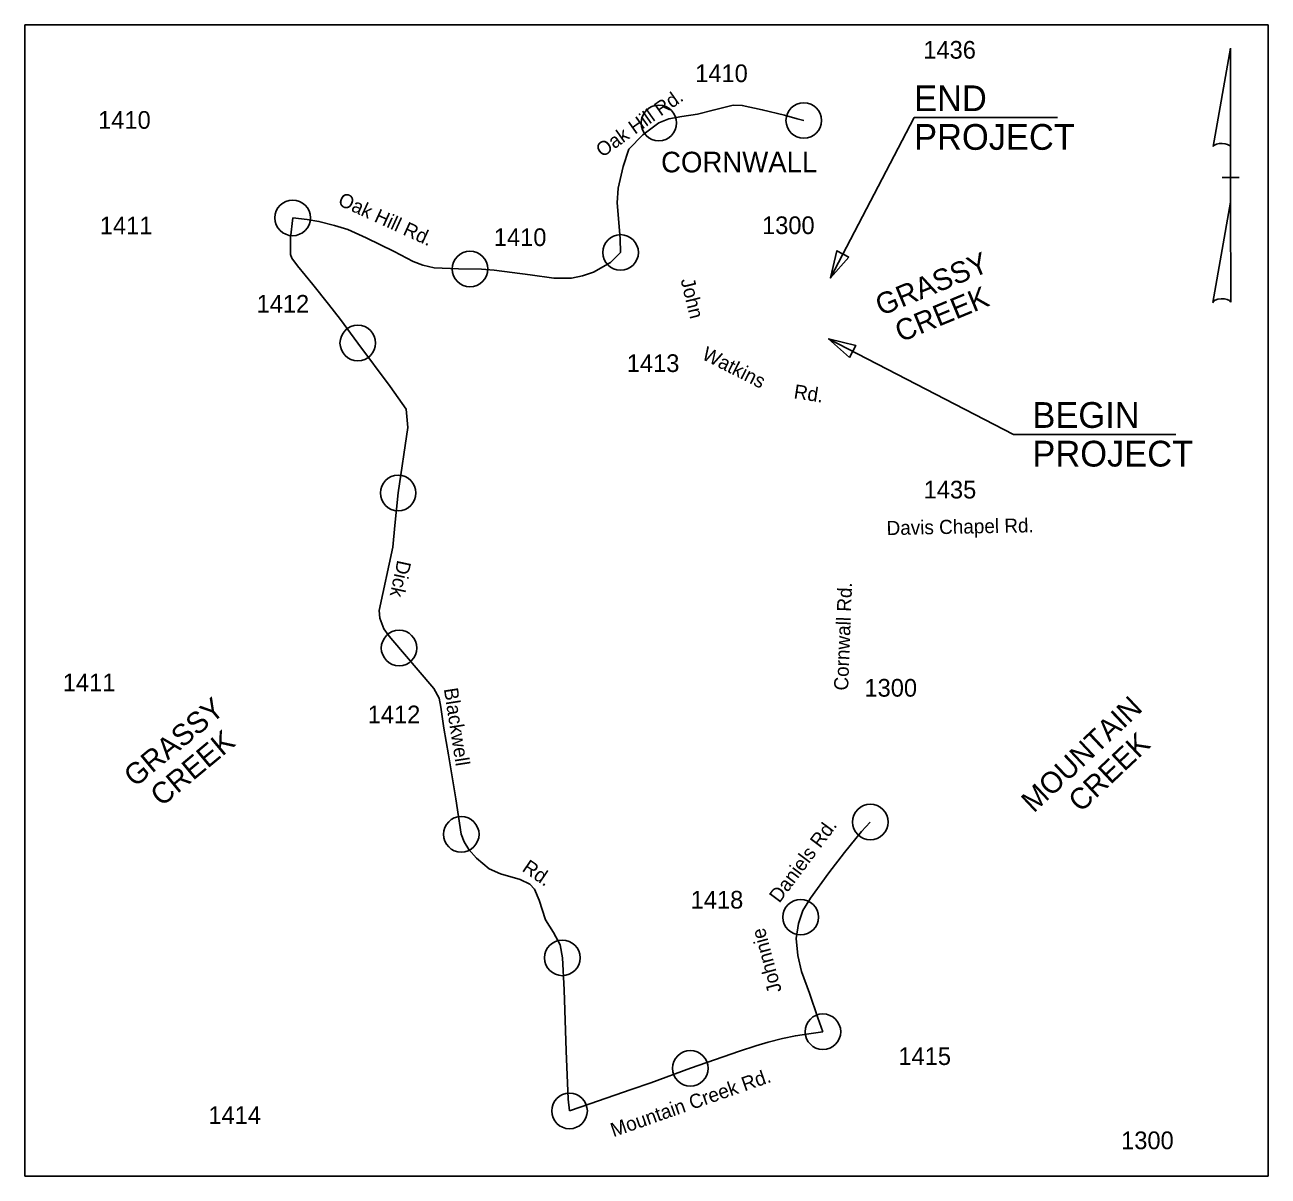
# Model space of a CAD drawing. Extents: x 2088807 to 2104187, y 980460 to 994694.
import ezdxf

# ---------------------------------------------------------------- set-up
doc = ezdxf.new("R2010")
doc.units = 0
for name, color, linetype in [('Exist Civil Demographics City Label', 7, 'Continuous'), ('Exist Hydrographic Creek Single Shore Label', 7, 'Continuous'), ('Exist Road Secondary Type 51 Label', 7, 'Continuous'), ('Exist Road Secondary Type 51 Number Label', 7, 'Continuous'), ('Old_Level_9', 7, 'Continuous'), ('Prop North Arrow for Plan Sheets CELL', 7, 'Continuous'), ('Sheet Block Title CELL', 7, 'Continuous'), ('Sheet Title CELL', 7, 'Continuous')]:
    doc.layers.add(name, color=color, linetype=linetype)

msp = doc.modelspace()

# ---------------------------------------------------------------- linework, layer by layer
at = {"layer": 'Old_Level_9'}
for p, q in [((2098772, 991565), (2099807, 993547)), ((2099807, 993547), (2101582, 993547)), ((2098750, 990810), (2101036, 989631)), ((2101036, 989631), (2103045, 989631))]:
    msp.add_line(p, q, dxfattribs=at)
for points in [[(2099001, 991822), (2098772, 991565), (2098853, 991900)], [(2099009, 990582), (2098750, 990810), (2099086, 990731)]]:
    msp.add_lwpolyline(points, close=True, dxfattribs=at)
at = {"layer": 'Prop North Arrow for Plan Sheets CELL'}
for p, q in [((2103507, 993190), (2103722, 994407)), ((2103723, 994407), (2103722, 994407)), ((2103723, 994407), (2103722, 994407)), ((2103723, 994407), (2103723, 993152)), ((2103723, 992501), (2103723, 993189)), ((2103723, 993152), (2103723, 993188)), ((2103618, 992806), (2103617, 992806)), ((2103712, 992806), (2103618, 992806)), ((2103620, 992806), (2103830, 992806)), ((2103723, 992501), (2103504, 991261)), ((2103725, 991266), (2103723, 992501))]:
    msp.add_line(p, q, dxfattribs=at)
for centre, start_param, end_param in [((2103615, 993177), 0.216388, 2.908219), ((2103615, 991257), 0.201328, 3.141593)]:
    msp.add_ellipse(centre, major_axis=(111, -1), ratio=0.461098, start_param=start_param, end_param=end_param, dxfattribs=at)
at = {"layer": 'Sheet Block Title CELL'}
msp.add_lwpolyline([(2088807, 994694), (2104187, 994694), (2104187, 980460), (2088807, 980460)], close=True, dxfattribs=at)
at = {"layer": 'Sheet Title CELL'}
for points in [[(2098442, 993511), (2098360, 993533), (2098204, 993576), (2097929, 993645), (2097682, 993697), (2097570, 993700), (2097320, 993641), (2097127, 993589), (2096932, 993559), (2096773, 993534), (2096649, 993481), (2096450, 993335), (2096277, 993156), (2096207, 992942), (2096148, 992676), (2096135, 992492), (2096153, 992250), (2096171, 992050), (2096176, 991880)], [(2092120, 992307), (2092094, 992059), (2092092, 991854), (2092109, 991808), (2092179, 991715), (2092370, 991483), (2092562, 991241), (2092710, 991053), (2092925, 990760), (2093326, 990221), (2093522, 989943), (2093544, 989715), (2093425, 988906), (2093385, 988506), (2093360, 988236), (2093190, 987455), (2093199, 987359), (2093247, 987227), (2093299, 987153), (2093333, 987110), (2093865, 986487), (2093933, 986369), (2093954, 986259), (2093989, 985997), (2094046, 985668), (2094140, 985124)], [(2096176, 991880), (2096052, 991754), (2095842, 991636), (2095705, 991591), (2095570, 991564), (2095352, 991564), (2095056, 991602), (2094614, 991660), (2094455, 991674), (2094171, 991677), (2093870, 991690), (2093730, 991724), (2093610, 991770), (2093376, 991893), (2093030, 992062), (2092802, 992164), (2092639, 992213), (2092444, 992263), (2092297, 992288), (2092120, 992307)], [(2094140, 985124), (2094205, 984686), (2094239, 984593), (2094298, 984500), (2094395, 984393), (2094552, 984259), (2094690, 984196), (2094935, 984128), (2095052, 984068), (2095111, 984008), (2095170, 983870), (2095248, 983627), (2095347, 983471), (2095427, 983319), (2095456, 983158), (2095479, 982762), (2095503, 982009), (2095528, 981413), (2095545, 981266)], [(2098679, 982245), (2098617, 982417), (2098512, 982721), (2098416, 982989), (2098369, 983188), (2098350, 983399), (2098378, 983583), (2098430, 983742), (2098525, 983897), (2098752, 984208), (2098944, 984460), (2099155, 984720), (2099265, 984838)], [(2095545, 981266), (2095797, 981353), (2096309, 981532), (2096549, 981614), (2097039, 981793), (2097648, 982006), (2097850, 982072), (2098001, 982116), (2098180, 982161), (2098339, 982195), (2098477, 982216), (2098679, 982245)]]:
    msp.add_lwpolyline(points, dxfattribs=at)
for centre in [(2098442, 993511), (2096649, 993481), (2092120, 992307), (2096176, 991880), (2094313, 991676), (2092925, 990760), (2093425, 988906), (2093436, 986989), (2099265, 984838), (2094205, 984686), (2098404, 983662), (2095456, 983158), (2098679, 982245), (2097039, 981793), (2095545, 981266)]:
    msp.add_circle(centre, 220, dxfattribs=at)

# ---------------------------------------------------------------- texts
at = {"layer": 'Exist Civil Demographics City Label'}
msp.add_text('CORNWALL', height=255, dxfattribs=at).set_placement((2096677, 992870))
at = {"layer": 'Exist Hydrographic Creek Single Shore Label'}
for s, rotation, p in [('GRASSY', 22.4756, (2099398, 991092)), ('CREEK', 22.4756, (2099640, 990766)), ('GRASSY', 39.8035, (2090170, 985259)), ('MOUNTAIN', 43.2868, (2101287, 984941)), ('CREEK', 39.8035, (2090498, 985020)), ('CREEK', 43.2868, (2101868, 984947))]:
    msp.add_text(s, height=262.5, rotation=rotation, dxfattribs=at).set_placement(p)
at = {"layer": 'Exist Road Secondary Type 51 Label'}
for s, rotation, p in [('Oak Hill Rd.', 35.197, (2095949, 993049)), ('Oak Hill Rd.', 335.4871, (2092667, 992472)), ('John', 283.9019, (2096917, 991540)), ('Watkins', 333.1694, (2097169, 990568)), ('Rd.', 351.2954, (2098311, 990078)), ('Davis Chapel Rd.', 1.1121, (2099468, 988385)), ('Dick', 257.7734, (2093416, 988084)), ('Cornwall Rd.', 87.846, (2098990, 986461)), ('Blackwell', 278.8375, (2093989, 986484)), ('Daniels Rd.', 53.2824, (2098140, 983827)), ('Rd.', 325.833, (2094946, 984239)), ('Johnnie', 105.1654, (2098171, 982750)), ('Mountain Creek Rd.', 19.2846, (2096088, 980940))]:
    msp.add_text(s, height=175, rotation=rotation, dxfattribs=at).set_placement(p)
at = {"layer": 'Exist Road Secondary Type 51 Number Label'}
for s, p in [('1436', (2099921, 994276)), ('1410', (2097099, 993986)), ('1410', (2089713, 993409)), ('1411', (2089734, 992104)), ('1300', (2097926, 992107)), ('1410', (2094608, 991959)), ('1412', (2091673, 991136)), ('1413', (2096253, 990402)), ('1435', (2099925, 988838)), ('1411', (2089276, 986455)), ('1300', (2099193, 986388)), ('1412', (2093048, 986059)), ('1418', (2097043, 983768)), ('1415', (2099613, 981834)), ('1414', (2091077, 981105)), ('1300', (2102368, 980793))]:
    msp.add_text(s, height=218.7, dxfattribs=at).set_placement(p)
at = {"layer": 'Old_Level_9'}
for s, p in [('END', (2099807, 993627)), ('PROJECT', (2099807, 993149)), ('BEGIN', (2101270, 989711)), ('PROJECT', (2101270, 989233))]:
    msp.add_text(s, height=318.7, rotation=360, dxfattribs=at).set_placement(p)

doc.saveas('drawing.dxf')
